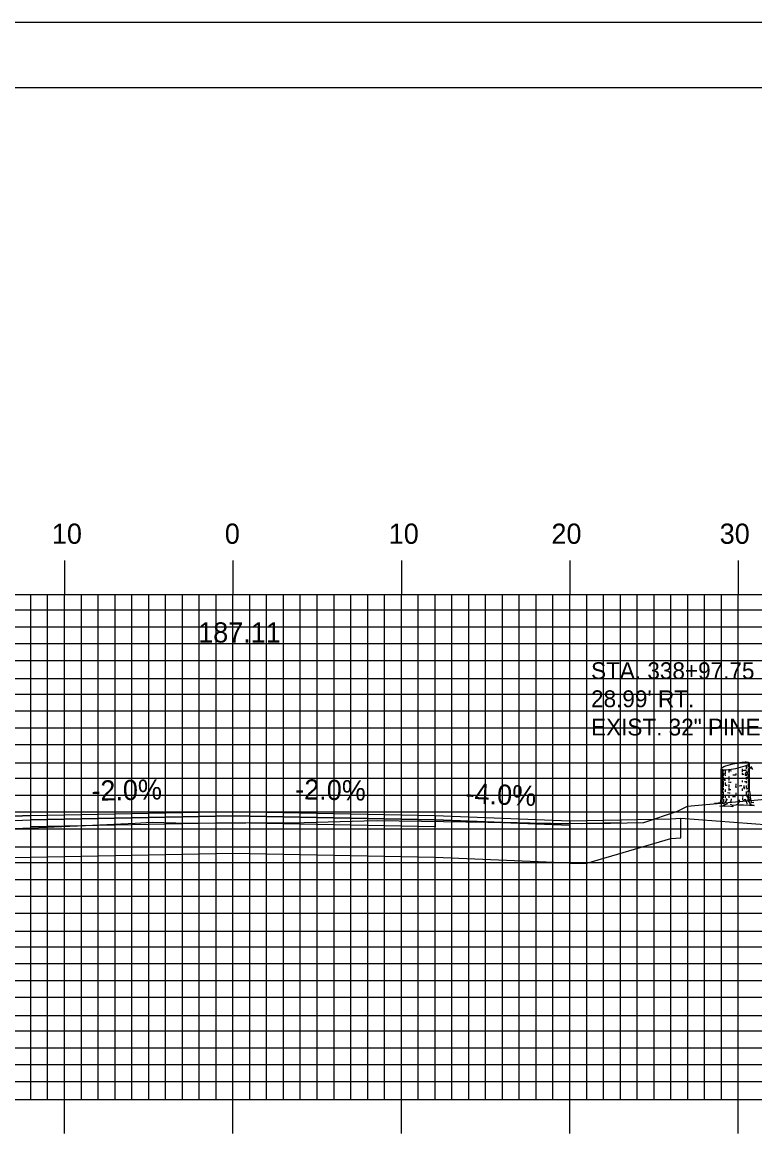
# Model space of a CAD drawing. Extents: x 1823966 to 1824309, y 442591 to 442811.
# Drawn here: x 1824119.3 to 1824162.8, y 442744.1 to 442810.5 of the extents above; entities that cross this region are included whole.
import ezdxf

# ---------------------------------------------------------------- set-up
doc = ezdxf.new("R2010")
doc.units = 0
for name, color, linetype in [('ANNOTATION', 7, 'Continuous'), ('BORDER', 7, 'Continuous'), ('D_Roadway_Centerline', 7, 'Continuous'), ('D_Roadway_Centerline_Text', 7, 'Continuous'), ('D_Roadway_Edge_Shoulder', 7, 'Continuous'), ('D_Roadway_Edge_TW', 7, 'Continuous'), ('D_Roadway_FinishedGrade', 7, 'Continuous'), ('D_Roadway_Pavement', 7, 'Continuous'), ('D_Roadway_SlopeLines', 7, 'Continuous'), ('D_Roadway_SubGrade', 7, 'Continuous'), ('D_Text_Monospaced', 7, 'Continuous'), ('H_V ANNOTATION', 7, 'Continuous'), ('MAJOR', 7, 'Continuous'), ('MINOR', 7, 'Continuous'), ('PLOT BOUNDARY', 7, 'Continuous'), ('S_Roadway_Centerline', 7, 'Continuous'), ('S_Trees_Conifer_Pay', 7, 'Continuous')]:
    doc.layers.add(name, color=color, linetype=linetype)

msp = doc.modelspace()

# ---------------------------------------------------------------- linework, layer by layer
at = {"layer": 'ANNOTATION'}
msp.add_line((1824151.822, 442763.135), (1824151.822, 442762.969), dxfattribs=at)
for points in [[(1824158.422, 442763.301), (1824167.853, 442762.587), (1824176.965, 442764.792)], [(1824151.822, 442763.135), (1824154.822, 442763.195), (1824154.822, 442763.029), (1824151.822, 442762.969)]]:
    msp.add_lwpolyline(points, dxfattribs=at)
at = {"layer": 'BORDER'}
msp.add_lwpolyline([(1823982.222, 442596.665), (1824302.222, 442596.665), (1824302.222, 442806.665), (1823982.222, 442806.665)], close=True, dxfattribs=at)
at = {"layer": 'D_Roadway_Centerline'}
msp.add_lwpolyline([(1824101.648, 442760.592), (1824108.628, 442762.337), (1824111.822, 442763.135), (1824119.822, 442763.455), (1824131.822, 442763.695), (1824143.822, 442763.455), (1824151.822, 442763.135), (1824157.822, 442763.255), (1824158.422, 442763.301), (1824167.853, 442762.587), (1824172.409, 442763.689), (1824176.965, 442764.792), (1824176.965, 442764.792), (1824178.215, 442765.061), (1824179.465, 442765.188)], dxfattribs=at)
at = {"layer": 'D_Roadway_Edge_Shoulder'}
for points in [[(1824119.822, 442763.455), (1824111.822, 442763.135), (1824111.822, 442762.885), (1824119.822, 442763.205)], [(1824143.822, 442763.455), (1824151.822, 442763.135), (1824151.822, 442762.885), (1824143.822, 442763.205)]]:
    msp.add_lwpolyline(points, close=True, dxfattribs=at)
at = {"layer": 'D_Roadway_Edge_TW'}
msp.add_lwpolyline([(1824119.822, 442763.205), (1824119.822, 442763.455), (1824131.822, 442763.695), (1824143.822, 442763.455), (1824143.822, 442763.205), (1824131.822, 442763.445)], close=True, dxfattribs=at)
at = {"layer": 'D_Roadway_FinishedGrade'}
msp.add_line((1824151.822, 442763.135), (1824157.822, 442763.255), dxfattribs=at)
for points in [[(1824157.822, 442763.255), (1824158.422, 442763.301)], [(1824157.822, 442762.085), (1824158.422, 442762.131)]]:
    msp.add_lwpolyline(points, dxfattribs=at)
at = {"layer": 'D_Roadway_Pavement'}
msp.add_lwpolyline([(1824119.822, 442762.788), (1824119.822, 442763.205), (1824131.822, 442763.445), (1824143.822, 442763.205), (1824143.822, 442762.788), (1824131.822, 442763.028)], close=True, dxfattribs=at)
at = {"layer": 'D_Roadway_SlopeLines'}
for p, q in [((1824158.422, 442762.131), (1824158.422, 442763.301)), ((1824151.822, 442763.135), (1824157.822, 442763.255)), ((1824151.822, 442763.135), (1824151.822, 442760.635)), ((1824152.822, 442760.635), (1824157.822, 442762.085)), ((1824151.822, 442760.635), (1824143.822, 442760.955)), ((1824151.822, 442760.635), (1824152.822, 442760.635))]:
    msp.add_line(p, q, dxfattribs=at)
at = {"layer": 'D_Roadway_SubGrade'}
msp.add_lwpolyline([(1824119.822, 442760.955), (1824101.648, 442760.592), (1824111.822, 442763.135), (1824111.822, 442762.885), (1824119.822, 442763.205), (1824131.822, 442763.445), (1824143.822, 442763.205), (1824151.822, 442762.885), (1824151.822, 442763.135), (1824151.822, 442760.635), (1824143.822, 442760.955), (1824131.822, 442761.195)], close=True, dxfattribs=at)
at = {"layer": 'MAJOR'}
for p, q in [((1824121.822, 442778.592), (1824121.822, 442776.588)), ((1824131.822, 442778.592), (1824131.822, 442776.588)), ((1824141.822, 442778.592), (1824141.822, 442776.588)), ((1824151.822, 442778.592), (1824151.822, 442776.588)), ((1824161.822, 442778.592), (1824161.822, 442776.588)), ((1823991.822, 442776.588), (1824271.822, 442776.588)), ((1824121.822, 442746.588), (1824121.822, 442776.588)), ((1824131.822, 442746.588), (1824131.822, 442776.588)), ((1824141.822, 442746.588), (1824141.822, 442776.588)), ((1824151.822, 442746.588), (1824151.822, 442776.588)), ((1824161.822, 442746.588), (1824161.822, 442776.588)), ((1823991.822, 442771.588), (1824271.822, 442771.588)), ((1823991.822, 442766.588), (1824271.822, 442766.588)), ((1823991.822, 442761.588), (1824271.822, 442761.588)), ((1823991.822, 442756.588), (1824271.822, 442756.588)), ((1823991.822, 442751.588), (1824271.822, 442751.588)), ((1823991.822, 442746.588), (1824271.822, 442746.588)), ((1823991.822, 442746.588), (1824271.822, 442746.588)), ((1824121.822, 442744.584), (1824121.822, 442746.588)), ((1824131.822, 442744.584), (1824131.822, 442746.588)), ((1824141.822, 442744.584), (1824141.822, 442746.588)), ((1824151.822, 442744.584), (1824151.822, 442746.588)), ((1824161.822, 442744.584), (1824161.822, 442746.588))]:
    msp.add_line(p, q, dxfattribs=at)
at = {"layer": 'MINOR'}
for p, q in [((1824119.822, 442746.588), (1824119.822, 442776.588)), ((1824120.822, 442746.588), (1824120.822, 442776.588)), ((1824122.822, 442746.588), (1824122.822, 442776.588)), ((1824123.822, 442746.588), (1824123.822, 442776.588)), ((1824124.822, 442746.588), (1824124.822, 442776.588)), ((1824125.822, 442746.588), (1824125.822, 442776.588)), ((1824126.822, 442746.588), (1824126.822, 442776.588)), ((1824127.822, 442746.588), (1824127.822, 442776.588)), ((1824128.822, 442746.588), (1824128.822, 442776.588)), ((1824129.822, 442746.588), (1824129.822, 442776.588)), ((1824130.822, 442746.588), (1824130.822, 442776.588)), ((1824132.822, 442746.588), (1824132.822, 442776.588)), ((1824133.822, 442746.588), (1824133.822, 442776.588)), ((1824134.822, 442746.588), (1824134.822, 442776.588)), ((1824135.822, 442746.588), (1824135.822, 442776.588)), ((1824136.822, 442746.588), (1824136.822, 442776.588)), ((1824137.822, 442746.588), (1824137.822, 442776.588)), ((1824138.822, 442746.588), (1824138.822, 442776.588)), ((1824139.822, 442746.588), (1824139.822, 442776.588)), ((1824140.822, 442746.588), (1824140.822, 442776.588)), ((1824142.822, 442746.588), (1824142.822, 442776.588)), ((1824143.822, 442746.588), (1824143.822, 442776.588)), ((1824144.822, 442746.588), (1824144.822, 442776.588)), ((1824145.822, 442746.588), (1824145.822, 442776.588)), ((1824146.822, 442746.588), (1824146.822, 442776.588)), ((1824147.822, 442746.588), (1824147.822, 442776.588)), ((1824148.822, 442746.588), (1824148.822, 442776.588)), ((1824149.822, 442746.588), (1824149.822, 442776.588)), ((1824150.822, 442746.588), (1824150.822, 442776.588)), ((1824152.822, 442746.588), (1824152.822, 442776.588)), ((1824153.822, 442746.588), (1824153.822, 442776.588)), ((1824154.822, 442746.588), (1824154.822, 442776.588)), ((1824155.822, 442746.588), (1824155.822, 442776.588)), ((1824156.822, 442746.588), (1824156.822, 442776.588)), ((1824157.822, 442746.588), (1824157.822, 442776.588)), ((1824158.822, 442746.588), (1824158.822, 442776.588)), ((1824159.822, 442746.588), (1824159.822, 442776.588)), ((1824160.822, 442746.588), (1824160.822, 442776.588)), ((1823991.822, 442775.665), (1824271.822, 442775.665)), ((1823991.822, 442774.665), (1824271.822, 442774.665)), ((1823991.822, 442773.665), (1824271.822, 442773.665)), ((1823991.822, 442772.665), (1824271.822, 442772.665)), ((1823991.822, 442770.665), (1824271.822, 442770.665)), ((1823991.822, 442769.665), (1824271.822, 442769.665)), ((1823991.822, 442768.665), (1824271.822, 442768.665)), ((1823991.822, 442767.665), (1824271.822, 442767.665)), ((1823991.822, 442765.665), (1824271.822, 442765.665)), ((1823991.822, 442764.665), (1824271.822, 442764.665)), ((1823991.822, 442763.665), (1824271.822, 442763.665)), ((1823991.822, 442762.665), (1824271.822, 442762.665)), ((1823991.822, 442760.665), (1824271.822, 442760.665)), ((1823991.822, 442759.665), (1824271.822, 442759.665)), ((1823991.822, 442758.665), (1824271.822, 442758.665)), ((1823991.822, 442757.665), (1824271.822, 442757.665)), ((1823991.822, 442755.665), (1824271.822, 442755.665)), ((1823991.822, 442754.665), (1824271.822, 442754.665)), ((1823991.822, 442753.665), (1824271.822, 442753.665)), ((1823991.822, 442752.665), (1824271.822, 442752.665)), ((1823991.822, 442750.665), (1824271.822, 442750.665)), ((1823991.822, 442749.665), (1824271.822, 442749.665)), ((1823991.822, 442748.665), (1824271.822, 442748.665)), ((1823991.822, 442747.665), (1824271.822, 442747.665))]:
    msp.add_line(p, q, dxfattribs=at)
at = {"layer": 'PLOT BOUNDARY'}
msp.add_lwpolyline([(1823966.035, 442590.547), (1824306.035, 442590.547), (1824306.035, 442810.547), (1823966.035, 442810.547)], close=True, dxfattribs=at)
at = {"layer": 'S_Roadway_Centerline'}
msp.add_lwpolyline([(1824115.129, 442762.531), (1824123.073, 442762.855), (1824126.017, 442762.994), (1824127.035, 442763.066), (1824129.115, 442762.996), (1824136.058, 442763.051), (1824139.619, 442763.137), (1824140.381, 442763.157), (1824146.958, 442763.064), (1824147.685, 442763.047), (1824147.938, 442763.061), (1824149.466, 442763.025), (1824150.71, 442762.995), (1824152.51, 442762.991), (1824154.238, 442763.003), (1824156.222, 442763.036), (1824158.214, 442763.72), (1824158.811, 442764.002), (1824165.394, 442764.598)], dxfattribs=at)
at = {"layer": 'S_Trees_Conifer_Pay'}
for p, q in [((1824160.815, 442764.501), (1824160.815, 442766.223)), ((1824160.862, 442766.186), (1824160.862, 442765.715)), ((1824160.92, 442766.174), (1824160.92, 442766.077)), ((1824160.92, 442766.003), (1824160.92, 442765.799)), ((1824161.046, 442766.167), (1824161.046, 442765.934)), ((1824161.265, 442766.187), (1824161.265, 442766.019)), ((1824161.671, 442765.955), (1824161.671, 442765.86)), ((1824162.061, 442766.229), (1824162.061, 442766.029)), ((1824162.061, 442765.972), (1824162.061, 442765.883)), ((1824162.29, 442766.425), (1824162.29, 442766.202)), ((1824162.29, 442766.113), (1824162.29, 442766.066)), ((1824162.407, 442766.486), (1824162.407, 442766.323)), ((1824162.407, 442766.256), (1824162.407, 442766.128)), ((1824162.479, 442764.911), (1824162.479, 442766.558)), ((1824160.862, 442765.65), (1824160.862, 442765.342)), ((1824160.862, 442765.295), (1824160.862, 442764.802)), ((1824160.92, 442765.741), (1824160.92, 442765.541)), ((1824160.92, 442765.494), (1824160.92, 442765.158)), ((1824161.046, 442765.894), (1824161.046, 442765.82)), ((1824161.046, 442765.416), (1824161.046, 442765.278)), ((1824161.265, 442765.782), (1824161.265, 442765.545)), ((1824161.265, 442765.3), (1824161.265, 442765.148)), ((1824161.671, 442765.342), (1824161.671, 442765.268)), ((1824162.061, 442765.535), (1824162.061, 442765.43)), ((1824162.29, 442765.731), (1824162.29, 442765.599)), ((1824162.29, 442765.488), (1824162.29, 442765.379)), ((1824162.347, 442765.93), (1824162.296, 442765.871)), ((1824162.407, 442765.941), (1824162.407, 442765.605)), ((1824162.407, 442765.568), (1824162.407, 442765.405)), ((1824162.407, 442765.358), (1824162.407, 442765.142)), ((1824160.862, 442764.749), (1824160.862, 442764.501)), ((1824160.92, 442765.105), (1824160.92, 442764.969)), ((1824160.92, 442764.87), (1824160.92, 442764.491)), ((1824161.046, 442765.006), (1824161.046, 442764.864)), ((1824161.265, 442765.105), (1824161.265, 442764.932)), ((1824161.265, 442764.654), (1824161.265, 442764.501)), ((1824161.671, 442765.243), (1824161.671, 442765.094)), ((1824161.671, 442764.802), (1824161.671, 442764.65)), ((1824162.061, 442765.064), (1824162.061, 442764.917)), ((1824162.061, 442764.685), (1824162.061, 442764.596)), ((1824162.29, 442765.243), (1824162.29, 442765.101)), ((1824162.29, 442764.874), (1824162.29, 442764.701)), ((1824162.407, 442765.111), (1824162.407, 442765.037)), ((1824162.407, 442764.996), (1824162.407, 442764.823)), ((1824161.046, 442764.602), (1824161.046, 442764.508)), ((1824161.046, 442764.108), (1824161.208, 442764.172)), ((1824161.483, 442764.044), (1824161.357, 442764.108))]:
    msp.add_line(p, q, dxfattribs=at)
for points in [[(1824162.262, 442766.019), (1824162.231, 442765.934), (1824162.227, 442765.867), (1824162.258, 442765.803)], [(1824162.296, 442766.056), (1824162.332, 442765.982), (1824162.38, 442766.039), (1824162.437, 442766.108), (1824162.53, 442766.301), (1824162.594, 442766.348), (1824162.625, 442766.355)], [(1824162.31, 442765.803), (1824162.347, 442765.93), (1824162.41, 442766.046), (1824162.441, 442766.113), (1824162.51, 442766.26)], [(1824162.525, 442766.289), (1824162.6, 442766.297), (1824162.672, 442766.198)], [(1824160.994, 442765.529), (1824160.988, 442765.624), (1824161.031, 442765.601), (1824161.031, 442765.507)], [(1824162.479, 442764.911), (1824162.53, 442764.65), (1824162.546, 442764.376), (1824162.604, 442764.251), (1824162.74, 442764.22), (1824162.51, 442764.182), (1824162.51, 442764.182), (1824162.515, 442764.135), (1824162.763, 442764.041), (1824162.489, 442764.057), (1824162.133, 442764.077), (1824161.811, 442764.067), (1824161.818, 442764.15), (1824161.67, 442764.067), (1824161.483, 442764.044), (1824161.507, 442763.976), (1824161.239, 442764.02), (1824161.019, 442763.993), (1824160.726, 442764.01), (1824161.015, 442764.067), (1824161.046, 442764.108), (1824160.883, 442764.166), (1824160.646, 442764.176), (1824160.405, 442764.176), (1824160.747, 442764.234), (1824160.788, 442764.314), (1824160.815, 442764.501)], [(1824162.133, 442765.13), (1824162.145, 442765.053), (1824162.193, 442765.064), (1824162.18, 442765.23)], [(1824162.405, 442764.769), (1824162.41, 442764.623), (1824162.458, 442764.555), (1824162.468, 442764.356)], [(1824160.863, 442764.454), (1824160.842, 442764.376), (1824160.821, 442764.281)], [(1824160.941, 442764.434), (1824160.947, 442764.318), (1824160.893, 442764.23), (1824160.883, 442764.166)], [(1824161.103, 442764.461), (1824161.103, 442764.329), (1824161.015, 442764.23)], [(1824161.33, 442764.22), (1824161.397, 442764.314), (1824161.424, 442764.454)], [(1824161.818, 442764.15), (1824161.892, 442764.291), (1824161.902, 442764.392)], [(1824162.069, 442764.518), (1824162.079, 442764.392), (1824162.153, 442764.349)], [(1824162.347, 442764.129), (1824162.332, 442764.267), (1824162.258, 442764.396)], [(1824162.306, 442764.623), (1824162.38, 442764.518), (1824162.384, 442764.345), (1824162.51, 442764.182)]]:
    msp.add_lwpolyline(points, dxfattribs=at)
for centre, radius, start, end in [((1824160.847, 442766.045), 0.0334, 163.94846, 180), ((1824160.847, 442766.045), 0.0334, 180, 196.05154), ((1824160.846, 442766.222), 0.0314, 156.51582, 169.2194), ((1824160.841, 442766.223), 0.0264, 169.2194, 180.03145), ((1824160.837, 442766.223), 0.0226, 180.03145, 191.7194), ((1824160.837, 442766.223), 0.0226, 191.7194, 203.40735), ((1824160.857, 442766.048), 0.0441, 196.05154, 210), ((1824160.866, 442766.213), 0.0527, 146.7194, 156.51582), ((1824160.841, 442766.224), 0.0264, 203.40735, 214.2194), ((1824160.845, 442766.227), 0.0314, 214.2194, 226.92298), ((1824160.873, 442766.057), 0.0624, 210, 228.74941), ((1824160.89, 442766.197), 0.0817, 132.38868, 146.7194), ((1824160.86, 442766.243), 0.0527, 226.92298, 236.7194), ((1824160.876, 442766.267), 0.0817, 236.7194, 251.05013), ((1824160.945, 442766.139), 0.172, 228.74941, 240), ((1824161.004, 442766.073), 0.251, 124.2194, 132.38868), ((1824160.93, 442766.427), 0.251, 251.05013, 259.2194), ((1824161.145, 442766.485), 0.571, 240, 240.33672), ((1824161.314, 442765.617), 0.802, 108.05939, 124.2194), ((1824161.033, 442766.968), 0.802, 259.2194, 275.37941), ((1824161.145, 442766.485), 0.571, 246.85973, 257.98457), ((1824162.671, 442761.456), 5.179, 101.7194, 108.05939), ((1824160.623, 442771.326), 5.179, 275.37941, 281.7194), ((1824161.647, 442770.235), 4.124, 264.6955, 266.73309), ((1824162.671, 442761.456), 5.179, 95.37941, 101.7194), ((1824160.623, 442771.326), 5.179, 281.7194, 288.05939), ((1824161.647, 442770.235), 4.124, 276.23804, 278.1032), ((1824162.26, 442765.813), 0.802, 79.2194, 95.37941), ((1824161.98, 442767.164), 0.802, 288.05939, 304.2194), ((1824162.148, 442766.717), 0.571, 278.1032, 284.36665), ((1824162.148, 442766.872), 0.571, 284.43166, 292.41325), ((1824162.148, 442766.717), 0.571, 297.0237, 300), ((1824162.363, 442766.355), 0.251, 71.05013, 79.2194), ((1824162.29, 442766.709), 0.251, 304.2194, 312.38868), ((1824162.347, 442766.527), 0.172, 300, 311.25059), ((1824162.347, 442766.372), 0.172, 300, 311.25059), ((1824162.418, 442766.514), 0.0817, 56.7194, 71.05013), ((1824162.404, 442766.584), 0.0817, 312.38868, 326.7194), ((1824162.419, 442766.444), 0.0624, 311.25059, 330), ((1824162.419, 442766.29), 0.0624, 311.25059, 330), ((1824162.434, 442766.539), 0.0527, 46.92298, 56.7194), ((1824162.449, 442766.554), 0.0314, 34.2194, 46.92298), ((1824162.428, 442766.568), 0.0527, 326.7194, 336.51582), ((1824162.435, 442766.435), 0.0441, 330, 343.94846), ((1824162.435, 442766.281), 0.0441, 330, 343.94846), ((1824162.453, 442766.557), 0.0264, 23.40735, 34.2194), ((1824162.447, 442766.559), 0.0314, 336.51582, 349.2194), ((1824162.456, 442766.559), 0.0226, 11.7194, 23.40735), ((1824162.456, 442766.559), 0.0226, 0.03145, 11.7194), ((1824162.452, 442766.559), 0.0264, 349.2194, 0.03145), ((1824162.446, 442766.432), 0.0334, 343.94846, 354.21506), ((1824162.446, 442766.278), 0.0334, 343.94846, 354.21506), ((1824160.847, 442765.598), 0.0334, 163.94846, 180), ((1824160.847, 442765.598), 0.0334, 180, 196.05154), ((1824160.847, 442765.388), 0.0334, 163.94846, 180), ((1824160.847, 442765.388), 0.0334, 180, 196.05154), ((1824160.857, 442765.601), 0.0441, 196.05154, 210), ((1824160.857, 442765.391), 0.0441, 196.05154, 210), ((1824160.873, 442765.61), 0.0624, 210, 228.74941), ((1824160.873, 442765.4), 0.0624, 210, 228.74941), ((1824160.945, 442765.693), 0.172, 228.74941, 240), ((1824160.945, 442765.483), 0.172, 228.74941, 240), ((1824161.145, 442766.038), 0.571, 240, 240.33672), ((1824161.145, 442765.828), 0.571, 240, 246.85973), ((1824161.146, 442766.273), 0.571, 240, 247.05866), ((1824161.646, 442769.555), 4.124, 264.08098, 266.66759), ((1824161.646, 442770.002), 4.124, 268.07512, 270), ((1824161.646, 442770.002), 4.124, 270, 270.35814), ((1824161.647, 442769.791), 4.124, 273.70524, 275.95043), ((1824161.646, 442770.002), 4.124, 275.78493, 277.05584), ((1824161.646, 442769.555), 4.124, 277.61247, 278.1032), ((1824162.146, 442766.038), 0.571, 278.1032, 286.92962), ((1824162.148, 442766.273), 0.571, 284.44928, 297.04285), ((1824162.146, 442766.038), 0.571, 297.18959, 300), ((1824162.146, 442765.828), 0.571, 297.18959, 300), ((1824162.346, 442765.693), 0.172, 300, 311.25059), ((1824162.346, 442765.483), 0.172, 300, 311.25059), ((1824162.418, 442765.61), 0.0624, 311.25059, 330), ((1824162.418, 442765.4), 0.0624, 311.25059, 330), ((1824162.434, 442765.601), 0.0441, 330, 343.94846), ((1824162.434, 442765.391), 0.0441, 330, 343.94846), ((1824162.444, 442765.598), 0.0334, 343.94846, 354.21506), ((1824162.444, 442765.388), 0.0334, 343.94846, 354.21506), ((1824162.445, 442765.834), 0.0334, 343.94846, 354.21506), ((1824160.847, 442765.151), 0.0334, 163.94846, 180), ((1824160.847, 442765.151), 0.0334, 180, 196.05154), ((1824160.847, 442764.954), 0.0334, 163.94846, 180), ((1824160.847, 442764.758), 0.0334, 163.94846, 180), ((1824160.847, 442764.758), 0.0334, 180, 196.05154), ((1824160.857, 442765.154), 0.0441, 196.05154, 210), ((1824160.857, 442764.761), 0.0441, 196.05154, 210), ((1824160.873, 442765.163), 0.0624, 210, 228.74941), ((1824160.873, 442764.77), 0.0624, 210, 228.74941), ((1824160.945, 442765.246), 0.172, 228.74941, 240), ((1824160.945, 442764.853), 0.172, 228.74941, 240), ((1824161.145, 442765.591), 0.571, 240, 246.85973), ((1824161.134, 442765.399), 0.571, 241.23686, 248.02677), ((1824161.145, 442765.198), 0.571, 240, 246.85973), ((1824161.145, 442765.828), 0.571, 259.27072, 261.8968), ((1824161.646, 442769.345), 4.124, 261.8968, 263.14738), ((1824161.646, 442768.911), 4.124, 263.49906, 265.83975), ((1824161.646, 442769.109), 4.124, 264.71603, 266.31934), ((1824161.646, 442769.345), 4.124, 270, 270.35814), ((1824161.646, 442769.345), 4.124, 273.14934, 275.45691), ((1824162.146, 442765.591), 0.571, 285.39827, 297.18959), ((1824162.146, 442765.198), 0.571, 288.50673, 297.27208), ((1824162.146, 442765.393), 0.571, 289.29072, 300), ((1824162.346, 442765.048), 0.172, 300, 311.25059), ((1824162.418, 442764.966), 0.0624, 311.25059, 330), ((1824162.434, 442764.957), 0.0441, 330, 343.94846), ((1824162.444, 442764.954), 0.0334, 343.94846, 354.21506), ((1824160.847, 442764.538), 0.0334, 163.94846, 180), ((1824160.847, 442764.538), 0.0334, 180, 196.05154), ((1824160.857, 442764.541), 0.0441, 196.05154, 210), ((1824160.873, 442764.55), 0.0624, 210, 228.74941), ((1824160.945, 442764.632), 0.172, 228.74941, 240), ((1824161.145, 442764.977), 0.571, 240, 244.53138), ((1824161.646, 442768.495), 4.124, 262.44379, 263.51202), ((1824161.646, 442768.715), 4.124, 267.81166, 270), ((1824161.646, 442768.715), 4.124, 270, 270.13279), ((1824161.646, 442768.715), 4.124, 275.78493, 276.78961), ((1824161.646, 442768.495), 4.124, 277.36842, 278.1032), ((1824162.146, 442764.977), 0.571, 278.1032, 281.63703), ((1824162.346, 442764.632), 0.172, 300, 311.25059), ((1824162.418, 442764.55), 0.0624, 311.25059, 330), ((1824162.434, 442764.541), 0.0441, 330, 343.94846), ((1824162.444, 442764.538), 0.0334, 343.94846, 354.21506)]:
    msp.add_arc(centre, radius, start, end, dxfattribs=at)

# ---------------------------------------------------------------- texts
at = {"layer": 'ANNOTATION'}
for s, rotation, p in [('-2.0%', 1.14576, (1824123.428, 442764.328)), ('-2.0%', 358.85424, (1824135.508, 442764.422)), ('-4.0%', 357.70939, (1824145.613, 442764.185))]:
    msp.add_text(s, height=1.2, rotation=rotation, dxfattribs=at).set_placement(p)
at = {"layer": 'D_Roadway_Centerline'}
for s, p in [('C', (1824131.817, 442763.695)), ('L', (1824131.822, 442763.688))]:
    msp.add_text(s, height=0.0146, dxfattribs=at).set_placement(p)
at = {"layer": 'D_Roadway_Centerline_Text'}
msp.add_text('187.11', height=1.2, dxfattribs=at).set_placement((1824129.756, 442773.725))
at = {"layer": 'D_Text_Monospaced'}
for s, height, p in [('STA. 338+97.75', 0.99996, (1824153.082, 442771.556)), ("28.99' RT.", 1, (1824153.082, 442769.888)), ('EXIST. 32" PINE', 0.99996, (1824153.082, 442768.208))]:
    msp.add_text(s, height=height, dxfattribs=at).set_placement(p)
at = {"layer": 'H_V ANNOTATION'}
for s, p in [('10', (1824121.072, 442779.588)), ('0', (1824131.34, 442779.588)), ('10', (1824141.072, 442779.588)), ('20', (1824150.73, 442779.588)), ('30', (1824160.719, 442779.588))]:
    msp.add_text(s, height=1.2, dxfattribs=at).set_placement(p)
at = {"layer": 'S_Roadway_Centerline'}
for s, p in [('L', (1824127.027, 442763.059)), ('C', (1824127.03, 442763.066))]:
    msp.add_text(s, height=0.0146, dxfattribs=at).set_placement(p)

doc.saveas('drawing.dxf')
